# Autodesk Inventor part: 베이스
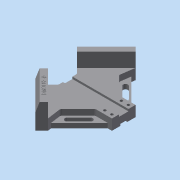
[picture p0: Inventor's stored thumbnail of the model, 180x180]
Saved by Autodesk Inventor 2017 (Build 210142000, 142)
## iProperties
Part Number: 베이스
Material: 일반
Document SubType Name: Modeling
Designer: 222
Density: 1 g/cm^3
Appearance: 기본값
Mass: 211.987 g
Surface Area: 406.293 cm^2
Volume: 211.987 cm^3
Author: 222
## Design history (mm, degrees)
sketch "스케치1"
  geometry: L1 (-84.853, 0)-(0, 84.853); L2 (0, 84.853)-(84.853, 0); L3 (84.853, 0)-(0, -84.853); L4 (0, -84.853)-(-84.853, 0); L5 (-84.853, 0)-(84.853, 0); L6 (0, 84.853)-(0, -84.853); L7 (-84.853, 0)-(35.147, 0); 1 further point
  constraints: 14 end point, 2 midpoint, 2 parallel, 1 equal length, 1 horizontal, 1 perpendicular
  dimensions: "d0" = 120 distance of L1.start L1.end; "d1" = 45 deg angle of L7 L1; "d2" = 120 distance of L1.end L2.end
extrude "돌출1" new body sketch "스케치1" distance "d3" = 18; taper "d4" = 0 deg
sketch "스케치2"
  geometry: L1 (0, -84.853)-(-84.853, 0) reference; L2 (-84.853, 0)-(0, 84.853) reference; L3 (0, 84.853)-(84.853, 0) reference; L4 (84.853, 0)-(0, -84.853) reference; L5 (64.853, -20)-(64.853, 20); 1 further point
  constraints: 2 end point, 2 point on line, 1 vertical
  dimensions: "d5" = 20 distance from line of L3.end L5
extrude "돌출2" cut sketch "스케치2" stored distance "d6" = 18; taper "d7" = 0 deg
sketch "스케치3"
  geometry: L1 (-49.497, -35.355)-(-30.147, -16.005); L2 (-30.147, -16.005)-(-30.147, 16.005); L3 (-30.147, 16.005)-(-49.497, 35.355); L4 (0, -84.853)-(-84.853, 0) reference; L5 (-84.853, 0)-(0, 84.853) reference; L6 (0, 84.853)-(64.853, 20) reference; L7 (64.853, 20)-(64.853, -20) reference; L8 (64.853, -20)-(0, -84.853) reference; 2 further points
  constraints: 6 end point, 2 parallel, 2 point on line, 1 horizontal alignment, 1 midpoint, 1 perpendicular, 1 vertical
  dimensions: "d9" = 50 distance between parallel lines of L5 L1; "d11" = 95 distance between parallel lines of L7 L2
extrude "돌출3" cut sketch "스케치3" stored distance "d12" = 18; taper "d13" = 0 deg
sketch "스케치4"
  geometry: L1 (64.853, 20)-(64.853, -20) reference; L2 (64.853, -20)-(0, -84.853) reference; L3 (0, -84.853)-(-49.497, -35.355) reference; L4 (-49.497, -35.355)-(-30.147, -16.005) reference; L5 (-30.147, -16.005)-(-30.147, 16.005) reference; L6 (-30.147, 16.005)-(-49.497, 35.355) reference; L7 (-49.497, 35.355)-(0, 84.853) reference; L8 (0, 84.853)-(64.853, 20) reference; L9 (10.607, -74.246)-(-38.891, -24.749); 1 further point
  constraints: 2 end point, 2 point on line, 1 parallel
  dimensions: "d14" = 15 distance between parallel lines of L9 L3
extrude "돌출4" join sketch "스케치4" distance "d15" = 24; taper "d16" = 0 deg
sketch "스케치5"
  geometry: L1 (64.853, 20)-(64.853, -20) reference; L2 (64.853, -20)-(10.607, -74.246) reference; L3 (-38.891, -24.749)-(10.607, -74.246) reference; L4 (-49.497, -35.355)-(-38.891, -24.749) reference; L5 (0, -84.853)-(-49.497, -35.355) reference; L6 (10.607, -74.246)-(0, -84.853) reference; L7 (0, 84.853)-(64.853, 20) reference; L8 (-49.497, 35.355)-(0, 84.853) reference; L9 (-30.147, 16.005)-(-49.497, 35.355) reference; L10 (-30.147, -16.005)-(-30.147, 16.005) reference; L11 (-38.891, -24.749)-(-30.147, -16.005) reference; L12 (10.607, -74.246)-(7.071, -49.497); L13 (7.071, -49.497)-(36.569, -20); L14 (36.569, -20)-(64.853, -20); L15 (9.723, -68.059)-(57.782, -20); L16 (18.385, -49.497)-(38.184, -29.698); L17 (21.213, -52.326)-(41.012, -32.527); L18 (35.355, -26.87)-(15.556, -46.669); A1 r 4 centre (18.385, -49.497) between (15.556, -46.669) and (21.213, -52.326); A2 r 4 centre (38.184, -29.698) between (41.012, -32.527) and (35.355, -26.87); 2 further points
  constraints: 16 end point, 4 parallel, 4 point on circle, 4 tangent, 2 centre point, 2 point on line, 1 horizontal, 1 midpoint
  dimensions: "d17" = 20 distance between parallel lines of L2 L13; "d18" = 30 distance from line of L5 L12.end; "d19" = 5 distance between parallel lines of L2 L15; "d20" = 12 distance between parallel lines of L2 L16; "d21" = 38 distance from line of L16.start L5; "d22" = 28 distance of L16.end L16.start; "d23" = 4 radius of A1
  node "절단 모서리 투영4"
extrude "돌출5" cut sketch "스케치5" stored distance "d24" = 24; taper "d25" = 0 deg
extrude "돌출6" cut sketch "스케치5" distance "d26" = 10; taper "d27" = 0 deg
sketch "스케치7"
  geometry: L1 (3, 6)-(0, 6); L2 (0, 6)-(0, -6); L3 (0, -6)-(3, -6); L4 (3, -6)-(3, 6); L5 (18, 8)-(14.5, 8); L6 (14.5, 8)-(14.5, -8); L7 (14.5, -8)-(18, -8); L8 (18, -8)-(18, 8); L9 (18, -16.005)-(18, 16.005) reference; 3 further points
  constraints: 16 end point, 4 parallel, 3 midpoint, 2 horizontal, 2 perpendicular, 1 coincident, 1 horizontal alignment
  dimensions: "d32" = 12 distance between parallel lines of L3 L1; "d33" = 16 distance of L5.end L6.end; "d34" = 3.5 distance between parallel lines of L8 L6; "d35" = 3 distance between parallel lines of L2 L4
extrude "돌출7" cut sketch "스케치7" stored distance "d36" = 10; taper "d37" = 0 deg
sketch "스케치9"
  geometry: L1 (64.853, 6)-(64.853, 20) reference; 2 further points
  dimensions: "d40" = 14 vertical distance of point (0, 0) point (58.853, 14); "d41" = 6 distance from line of L1 point (58.853, 14)
hole "구멍1" sketch "스케치9" at (58.853, 14) diameter "d42" = 4.5; stored, may be unused: countersink angle "d46" = 90 deg, drill point angle "d48" = 118 deg; dims "d43" = 6, "d44" = 8, "d45" = 8, "d47" = 8
fillet "모깎기1" dims "d55" = 5
sketch "스케치10"
  geometry: L1 (10.607, -74.246)-(-38.891, -24.749) reference; L2 (-38.891, -24.749)-(-49.497, -35.355) reference; 2 further points
  constraints: 1 other
  dimensions: "d56" = 5 distance from line of L1 point (-17.678, -53.033); "d57" = 35 distance from line of point (-17.678, -53.033) L2
feature "엠보싱1" sketch "스케치10" dims "d0" = 120, "d1" = 45 deg, "d2" = 120, "d9" = 50, "d11" = 95, "d58" = 0.5, "d59" = 0
chamfer "모따기1" distance "d60" = 5; stored, may be unused: second distance "d61" = 15, angle "d62" = 45 deg
chamfer "모따기2" distance "d63" = 15; stored, may be unused: second distance "d64" = 5, angle "d65" = 45 deg
fillet "모깎기2" dims "d66" = 5
node "솔리드1"
mirror "미러1"
pattern_linear "직사각형 패턴1" dims "d51" = 12, "d54" = 28
node "절단 모서리 투영1"
node "절단 모서리 투영2"
node "절단 모서리 투영3"
